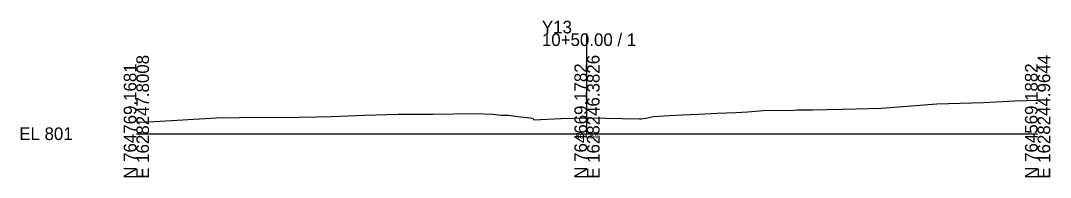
# Model space of a CAD drawing. Extents: x -26 to 203, y -10 to 3517.
# Drawn here: x -25.7 to 202.8, y 990.3 to 1025.1 of the extents above; entities that cross this region are included whole.
import ezdxf

# ---------------------------------------------------------------- set-up
doc = ezdxf.new("R2010")
doc.units = 0
for name, color, linetype in [('Default', 7, 'Continuous'), ('Exist Cross Section Cell', 7, 'Continuous'), ('Exist XS Center Line Elevation Label', 7, 'Continuous'), ('Exist XS Ground Line', 7, 'Continuous')]:
    doc.layers.add(name, color=color, linetype=linetype)

msp = doc.modelspace()

# ---------------------------------------------------------------- linework, layer by layer
at = {"layer": 'Exist Cross Section Cell'}
for p, q in [((100, 1000), (100, 1022.26)), ((0, 1000), (100, 1000)), ((100, 1000), (200, 1000))]:
    msp.add_line(p, q, dxfattribs=at)
at = {"layer": 'Exist XS Ground Line'}
msp.add_lwpolyline([(0, 1002.58), (4.05, 1002.74), (17.79, 1003.54), (22.83, 1003.59), (36.15, 1003.66), (39.99, 1003.77), (43.24, 1003.84), (50.64, 1004.1), (58.06, 1004.33), (65.79, 1004.34), (75.01, 1004.46), (79.11, 1004.35), (80.9, 1004.13), (82.5, 1004.08), (84.56, 1003.84), (87.47, 1003.49), (88.07, 1003.34), (88.24, 1003.07), (94.2, 1003.38), (100, 1003.54), (100.3, 1003.55), (111.67, 1003.31), (112.05, 1003.3), (113.03, 1003.44), (114.74, 1003.82), (118.25, 1004.06), (121.12, 1004.22), (124.85, 1004.37), (128.88, 1004.57), (133.03, 1004.73), (135.71, 1004.85), (139.11, 1005.12), (145.89, 1005.24), (146.74, 1005.27), (150.06, 1005.27), (159.68, 1005.51), (165.35, 1005.66), (177.66, 1006.62), (187.96, 1006.92), (194.94, 1007.26), (200, 1007.42)], dxfattribs=at)

# ---------------------------------------------------------------- texts
at = {"layer": 'Default'}
msp.add_text('-', height=0.0001, dxfattribs=at).set_placement((0, 1000))
at = {"layer": 'Exist Cross Section Cell'}
for s, p in [('Y13', (90, 1022.26)), ('10+50.00 / 1', (90, 1019.46)), ('EL 801', (-26, 998.6))]:
    msp.add_text(s, height=2.8, dxfattribs=at).set_placement(p)
for s, p in [('E 1628247.8008', (2.8, 990)), ('E 1628246.3826', (102.8, 990)), ('E 1628244.9644', (202.8, 990)), ('N 764769.1681', (0, 990)), ('N 764669.1782', (100, 990)), ('N 764569.1882', (200, 990))]:
    msp.add_text(s, height=2.8, rotation=90, dxfattribs=at).set_placement(p)
at = {"layer": 'Exist XS Center Line Elevation Label'}
msp.add_text('804.54', height=1.2, dxfattribs=at).set_placement((97.43, 998.94))

doc.saveas('drawing.dxf')
